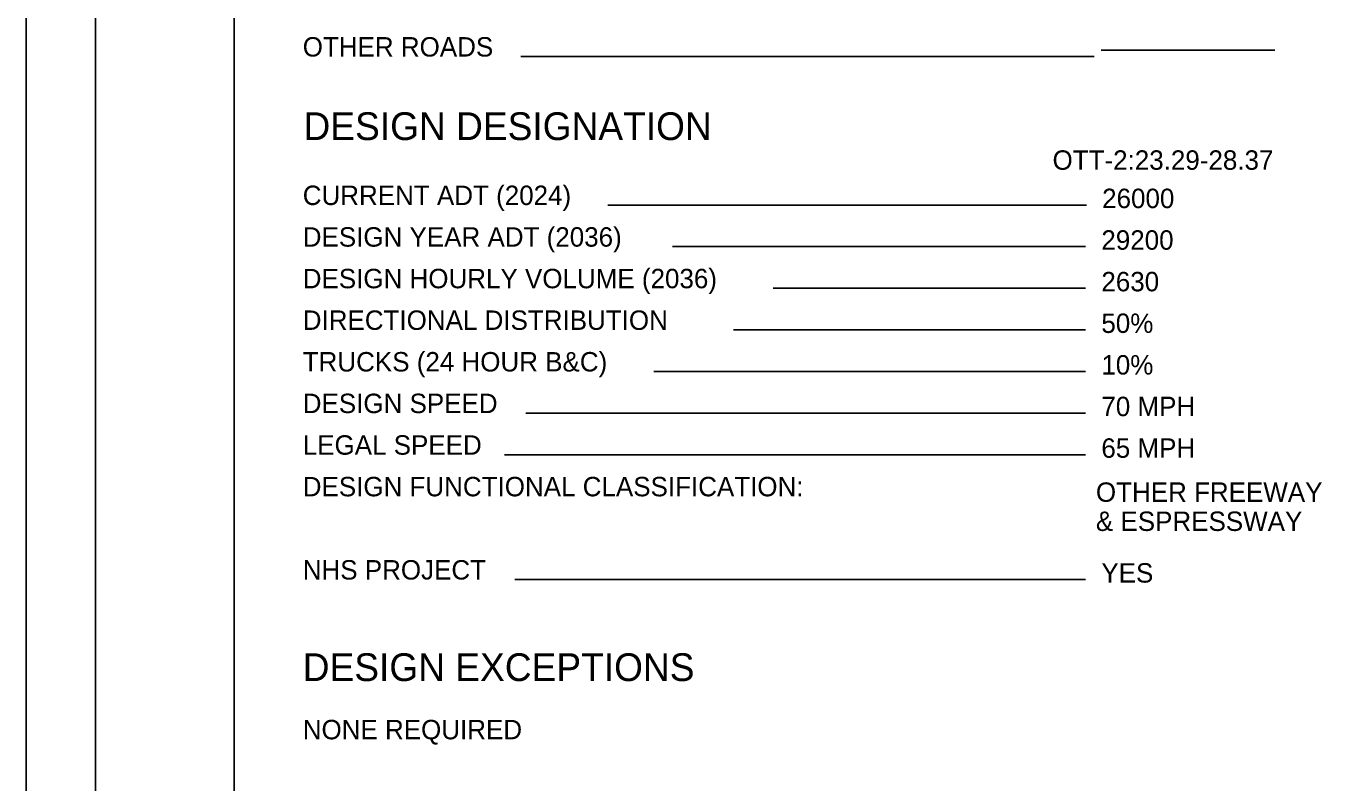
# Model space of a CAD drawing. Extents: x 0 to 34, y 0 to 22.
# Drawn here: x 0 to 9.38, y 5.64 to 11.1 of the extents above; entities that cross this region are included whole.
import ezdxf

# ---------------------------------------------------------------- set-up
doc = ezdxf.new("R2010")
doc.units = 0
for name, color, linetype in [('SH_Border', 7, 'Continuous'), ('SH_Cut_Line', 7, 'Continuous'), ('SH_Data', 7, 'Continuous'), ('SH_Text', 7, 'Continuous')]:
    doc.layers.add(name, color=color, linetype=linetype)

msp = doc.modelspace()

# ---------------------------------------------------------------- linework, layer by layer
at = {"layer": 'SH_Border'}
for points in [[(0.5, 21.5), (1.5, 21.5), (1.5, 0.5), (0.5, 0.5)], [(1.5, 21.5), (33.5, 21.5), (33.5, 0.5), (1.5, 0.5)]]:
    msp.add_lwpolyline(points, close=True, dxfattribs=at)
at = {"layer": 'SH_Cut_Line'}
msp.add_lwpolyline([(0, 0), (34, 0), (34, 22), (0, 22)], close=True, dxfattribs=at)
at = {"layer": 'SH_Data'}
for p, q in [((9, 10.9223), (7.75, 10.9223)), ((7.7, 10.8767), (3.5657, 10.8767)), ((7.6424, 9.8062), (4.1936, 9.8062)), ((7.6368, 9.5062), (4.6592, 9.5062)), ((7.6368, 9.2062), (5.3852, 9.2062)), ((7.6368, 8.9062), (5.0988, 8.9062)), ((7.6368, 8.6062), (4.5259, 8.6062)), ((7.6368, 8.3062), (3.6035, 8.3062)), ((7.6368, 8.0062), (3.4488, 8.0062)), ((7.6368, 7.1062), (3.5243, 7.1062))]:
    msp.add_line(p, q, dxfattribs=at)

# ---------------------------------------------------------------- texts
msp.add_text('DESIGN DESIGNATION', height=0.2, dxfattribs=at).set_placement((2, 10.2747))
at = {"layer": 'SH_Text'}
for s, height, p in [('OTHER ROADS', 0.14, (1.9944, 10.8767)), ('OTT-2:23.29-28.37', 0.14, (7.3988, 10.0604)), ('CURRENT ADT (2024)', 0.14, (1.9944, 9.8062)), ('26000', 0.14, (7.7563, 9.7841)), ('DESIGN YEAR ADT (2036)', 0.14, (1.9944, 9.5062)), ('29200', 0.14, (7.7507, 9.4841)), ('DESIGN HOURLY VOLUME (2036)', 0.14, (1.9944, 9.2062)), ('2630', 0.14, (7.7507, 9.1841)), ('DIRECTIONAL DISTRIBUTION', 0.14, (1.9944, 8.9062)), ('50%', 0.14, (7.7507, 8.8841)), ('TRUCKS (24 HOUR B&C)', 0.14, (1.9944, 8.6062)), ('10%', 0.14, (7.7507, 8.5841)), ('DESIGN SPEED', 0.14, (1.9944, 8.3062)), ('70 MPH', 0.14, (7.7507, 8.2841)), ('LEGAL SPEED', 0.14, (1.9944, 8.0062)), ('65 MPH', 0.14, (7.7507, 7.9841)), ('DESIGN FUNCTIONAL CLASSIFICATION:', 0.14, (1.9944, 7.7062)), ('OTHER FREEWAY', 0.14, (7.7114, 7.6664)), ('& ESPRESSWAY', 0.14, (7.7114, 7.4564)), ('NHS PROJECT', 0.14, (1.9944, 7.1062)), ('YES', 0.14, (7.7507, 7.0841)), ('DESIGN EXCEPTIONS', 0.2, (1.9944, 6.3744)), ('NONE REQUIRED', 0.14, (1.9944, 5.9544))]:
    msp.add_text(s, height=height, dxfattribs=at).set_placement(p)

doc.saveas('drawing.dxf')
